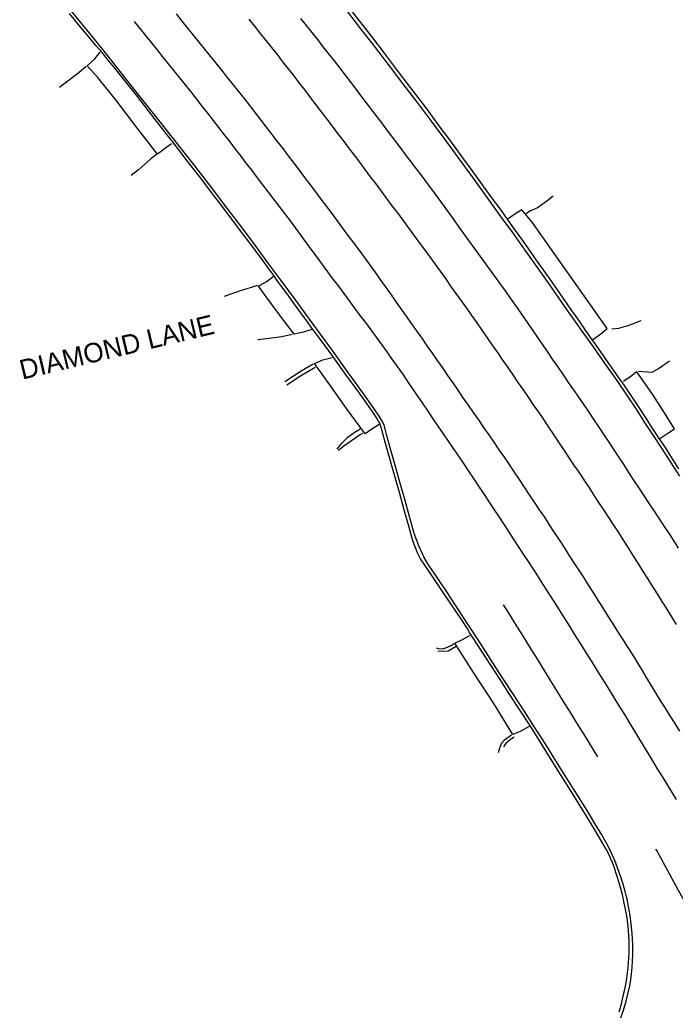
# Model space of a CAD drawing. Extents: x 1970211 to 1973046, y 801032 to 804001.
# Drawn here: x 1972654.2 to 1972835.3, y 801305.3 to 801579.3 of the extents above; entities that cross this region are included whole.
import ezdxf

# ---------------------------------------------------------------- set-up
doc = ezdxf.new("R2010")
doc.units = 0
for name, color, linetype in [('RD_EX_Conc', 7, 'Continuous'), ('RD_EX_Road', 7, 'Continuous'), ('RD_EX_Road_Paint', 7, 'Continuous'), ('RD_TX_RoadID', 7, 'Continuous')]:
    doc.layers.add(name, color=color, linetype=linetype)

msp = doc.modelspace()

# ---------------------------------------------------------------- linework, layer by layer
at = {"layer": 'RD_EX_Conc'}
for points in [[(1972745.68, 801581.99), (1972748.76, 801578.08), (1972751.65, 801574.34), (1972754.91, 801570.07), (1972759.07, 801564.57), (1972763.27, 801559.01), (1972766.66, 801554.53), (1972769.79, 801550.36), (1972773.24, 801545.72), (1972776.6, 801541.15), (1972779.45, 801537.2), (1972782.04, 801533.6), (1972784.61, 801530.07), (1972786.94, 801526.88), (1972788.82, 801524.26), (1972790.66, 801521.68), (1972792.86, 801518.58), (1972795.24, 801515.23), (1972797.6, 801511.88), (1972800.21, 801508.15), (1972803.36, 801503.66), (1972806.41, 801499.28), (1972808.77, 801495.9), (1972810.5, 801493.4), (1972811.7, 801491.67), (1972812.91, 801489.93), (1972814.66, 801487.43), (1972816.51, 801484.8), (1972817.98, 801482.67), (1972819.12, 801481.04), (1972819.96, 801479.91), (1972821.05, 801478.4), (1972822.93, 801475.62), (1972825.14, 801472.28), (1972827.22, 801469.1), (1972828.92, 801466.46), (1972830.02, 801464.76), (1972830.84, 801463.49), (1972831.75, 801462.13), (1972832.71, 801460.67), (1972833.7, 801459.13), (1972834.85, 801457.33), (1972836.29, 801455.1)], [(1972819.87, 801304.88), (1972820.39, 801306.73), (1972820.99, 801309.16), (1972821.51, 801311.47), (1972821.81, 801312.96), (1972822, 801314.16), (1972822.2, 801315.62), (1972822.37, 801317.13), (1972822.48, 801318.47), (1972822.56, 801319.8), (1972822.62, 801321.25), (1972822.64, 801322.81), (1972822.61, 801324.43), (1972822.55, 801325.96), (1972822.48, 801327.26), (1972822.35, 801328.58), (1972822.16, 801330.17), (1972821.9, 801331.9), (1972821.56, 801333.67), (1972821.19, 801335.37), (1972820.83, 801336.9), (1972820.5, 801338.22), (1972820.23, 801339.28), (1972819.86, 801340.57), (1972819.25, 801342.54), (1972818.57, 801344.6), (1972817.99, 801346.14), (1972817.46, 801347.35), (1972816.96, 801348.44), (1972816.22, 801349.87), (1972815, 801352.07), (1972813.15, 801355.21), (1972810.57, 801359.45), (1972807.41, 801364.52), (1972803.86, 801370.2), (1972800.43, 801375.68), (1972797.65, 801380.16), (1972795.14, 801384.16), (1972792.54, 801388.19), (1972789.86, 801392.3), (1972787.14, 801396.53), (1972784.4, 801400.8), (1972781.67, 801405), (1972779.59, 801408.18), (1972778.81, 801409.35), (1972778.54, 801409.77), (1972777.99, 801410.7), (1972776.06, 801413.69), (1972771.62, 801420.28), (1972767.13, 801426.96), (1972765, 801430.22), (1972764.14, 801431.82), (1972763.44, 801433.51), (1972762.87, 801435.2), (1972762.38, 801436.79), (1972761.71, 801439.2), (1972760.56, 801443.36), (1972759.13, 801448.52), (1972757.59, 801453.94), (1972756.2, 801458.82), (1972755.2, 801462.41), (1972754.5, 801464.89), (1972754.05, 801466.47), (1972753.77, 801467.38), (1972753.59, 801467.87), (1972753.38, 801468.28), (1972753, 801468.91), (1972752.03, 801470.34), (1972750.08, 801473.14), (1972747.34, 801477.01), (1972743.98, 801481.66), (1972740.63, 801486.29), (1972737.88, 801490.07), (1972735.89, 801492.8), (1972734.77, 801494.29), (1972733.72, 801495.71), (1972731.9, 801498.21), (1972729.84, 801501.04), (1972728.09, 801503.44), (1972726.65, 801505.4), (1972725.54, 801506.93), (1972724.76, 801508), (1972724.34, 801508.61), (1972723.97, 801509.16), (1972723.35, 801510.07), (1972721.97, 801511.96), (1972719.34, 801515.48), (1972716.13, 801519.75), (1972713.02, 801523.88), (1972710.03, 801527.83), (1972707.19, 801531.55), (1972704.21, 801535.45), (1972700.77, 801539.95), (1972697.92, 801543.66), (1972696.69, 801545.23), (1972695.64, 801546.56), (1972693.27, 801549.6), (1972690.06, 801553.75), (1972686.44, 801558.4), (1972683.04, 801562.72), (1972680.52, 801565.88), (1972678.68, 801568.14), (1972677.35, 801569.76), (1972676.48, 801570.8), (1972676, 801571.35), (1972675.27, 801572.19), (1972673.65, 801574.12), (1972671.19, 801577.08), (1972667.96, 801581)], [(1972696.13, 801545.02), (1972694.22, 801543.56), (1972692.31, 801542.12), (1972686.22, 801550), (1972681.01, 801556.76), (1972675.83, 801563.34), (1972672.82, 801566.6), (1972675, 801568.46), (1972676.43, 801570.33)], [(1972812.6, 801490.89), (1972814.78, 801492.4), (1972816.54, 801493.94), (1972811.93, 801500.41), (1972804.84, 801510.49), (1972795.85, 801523.29), (1972793, 801526.7), (1972791.03, 801525.49), (1972789.17, 801524.21)], [(1972734.94, 801493.66), (1972732.6, 801492.87), (1972730.03, 801492.33), (1972724.89, 801499.16), (1972720.22, 801505.57), (1972722.62, 801506.95), (1972724.27, 801508.25)], [(1972753.51, 801467.3), (1972751.49, 801466.04), (1972749.63, 801464.73), (1972744.53, 801471.76), (1972739.92, 801478.33), (1972735.69, 801484.23), (1972737.92, 801485.21), (1972740.54, 801485.88)], [(1972735.28, 801484.03), (1972732, 801482.05), (1972727.48, 801479.16)], [(1972831.12, 801463.48), (1972833.3, 801464.92), (1972835.16, 801466.1), (1972831.7, 801471.61), (1972828.85, 801476.03), (1972824.72, 801481.91), (1972822.79, 801480.44), (1972821.04, 801479.25)], [(1972748.9, 801464.88), (1972748.31, 801464.46), (1972743.78, 801461.39), (1972742.29, 801460.12)], [(1972794.94, 801383.77), (1972792.65, 801382.55), (1972790.44, 801381.62), (1972785.19, 801390.17), (1972779.64, 801398.71), (1972774.43, 801406.83), (1972776.37, 801407.75), (1972778.59, 801408.98)], [(1972769.28, 801405.52), (1972769.93, 801405.35), (1972771.07, 801405.29), (1972771.96, 801405.56), (1972773.44, 801406.22), (1972774.23, 801406.79)], [(1972790.8, 801380.8), (1972789.83, 801380.16), (1972789.12, 801379.56), (1972788.41, 801378.99), (1972787.92, 801378.17)]]:
    msp.add_lwpolyline(points, dxfattribs=at)
at = {"layer": 'RD_EX_Road'}
for points in [[(1972820.26, 801302.91), (1972821.06, 801305.35), (1972821.8, 801307.85), (1972822.37, 801310.09), (1972822.77, 801312.01), (1972823.06, 801313.77), (1972823.27, 801315.42), (1972823.43, 801317.14), (1972823.56, 801318.94), (1972823.64, 801320.55), (1972823.67, 801321.98), (1972823.65, 801323.43), (1972823.58, 801324.95), (1972823.47, 801326.58), (1972823.31, 801328.29), (1972823.11, 801329.93), (1972822.88, 801331.47), (1972822.63, 801332.97), (1972822.37, 801334.42), (1972822.12, 801335.64), (1972821.87, 801336.71), (1972821.48, 801338.19), (1972820.94, 801340.15), (1972820.25, 801342.35), (1972819.44, 801344.7), (1972818.66, 801346.76), (1972817.86, 801348.59), (1972816.68, 801350.91), (1972815.07, 801353.8), (1972813.17, 801357), (1972810.98, 801360.53), (1972808.33, 801364.76), (1972805.3, 801369.62), (1972802.36, 801374.32), (1972799.55, 801378.79), (1972796.63, 801383.38), (1972793.59, 801388.09), (1972790.66, 801392.61), (1972787.83, 801396.98), (1972784.75, 801401.72), (1972781.4, 801406.91), (1972777.89, 801412.34), (1972774.46, 801417.64), (1972772.43, 801420.75), (1972771.76, 801421.75), (1972770.87, 801423.07), (1972769.57, 801424.99), (1972768.32, 801426.79), (1972767.17, 801428.49), (1972765.89, 801430.77), (1972764.46, 801433.76), (1972763.12, 801437.48), (1972761.91, 801441.85), (1972760.69, 801446.29), (1972759.44, 801450.78), (1972758.05, 801455.75), (1972756.61, 801460.9), (1972755.76, 801463.96), (1972755.51, 801464.9), (1972755.32, 801465.66), (1972755.09, 801466.55), (1972754.79, 801467.4), (1972754.36, 801468.27), (1972753.5, 801469.64), (1972752.15, 801471.64), (1972750.17, 801474.46), (1972747.61, 801478.06), (1972744.72, 801482.08), (1972741.56, 801486.48), (1972738.08, 801491.29), (1972734.3, 801496.48), (1972730.41, 801501.79), (1972726.47, 801507.13), (1972722.6, 801512.38), (1972718.79, 801517.56), (1972714.81, 801522.86), (1972710.65, 801528.34), (1972706.34, 801533.96), (1972701.91, 801539.7), (1972697.43, 801545.44), (1972692.99, 801551.09), (1972688.98, 801556.18), (1972685.41, 801560.7), (1972682, 801565.01), (1972678.62, 801569.25), (1972674.84, 801573.94), (1972670.64, 801579.09), (1972666.32, 801584.32)], [(1972836.62, 801453.04), (1972834.12, 801456.92), (1972831.63, 801460.77), (1972829.12, 801464.61), (1972826.79, 801468.18), (1972824.6, 801471.55), (1972822.12, 801475.31), (1972819.28, 801479.53), (1972816.12, 801484.06), (1972812.72, 801488.79), (1972809.46, 801493.4), (1972806.36, 801497.83), (1972803.3, 801502.21), (1972800.24, 801506.58), (1972797.11, 801511.02), (1972793.9, 801515.55), (1972790.61, 801520.15), (1972787.19, 801524.87), (1972783.47, 801530.01), (1972779.47, 801535.56), (1972775.45, 801541.13), (1972771.46, 801546.59), (1972767.7, 801551.66), (1972764.13, 801556.37), (1972760.38, 801561.31), (1972756.43, 801566.51), (1972752.48, 801571.64), (1972748.5, 801576.78), (1972743.91, 801582.67)], [(1972672.54, 801566.36), (1972670.52, 801564.65), (1972666.79, 801561.73), (1972665.2, 801560.58)], [(1972692.03, 801542), (1972690.31, 801540.71), (1972687.02, 801537.83), (1972685.02, 801536.18)], [(1972801.65, 801530.48), (1972799.86, 801529.13), (1972797.28, 801527.29), (1972795.21, 801526.32), (1972794.14, 801525.65)], [(1972720, 801505.79), (1972715.14, 801504.29), (1972710.69, 801502.77)], [(1972817.87, 801493.76), (1972819.76, 801494.02), (1972822.33, 801494.72), (1972825.96, 801496.07)], [(1972729.52, 801492.25), (1972726.59, 801491.61), (1972722.4, 801491.04), (1972719.89, 801490.75)], [(1972728.01, 801478.33), (1972731.8, 801480.83), (1972735.89, 801483.17)], [(1972833.8, 801484.83), (1972831.02, 801482.91), (1972828.88, 801481.72), (1972825.2, 801482.01)], [(1972748.32, 801466.08), (1972746.37, 801464.82), (1972744.64, 801463.52), (1972742.82, 801461.83), (1972741.84, 801460.5)], [(1972774.77, 801405.88), (1972772.56, 801404.68), (1972771.26, 801404.52), (1972769.7, 801404.66)], [(1972786.53, 801376.63), (1972786.86, 801377.91), (1972787.45, 801379.25), (1972788.18, 801380.08), (1972790.13, 801381.46)]]:
    msp.add_lwpolyline(points, dxfattribs=at)
at = {"layer": 'RD_EX_Road_Paint'}
for points in [[(1972685.85, 801578.85), (1972687.41, 801576.9), (1972688.97, 801574.95), (1972690.53, 801572.99), (1972692.09, 801571.04), (1972693.65, 801569.09), (1972695.21, 801567.13), (1972696.77, 801565.18), (1972698.33, 801563.23), (1972699.89, 801561.27), (1972701.45, 801559.32), (1972703.01, 801557.37), (1972704.57, 801555.41), (1972706.1, 801553.44), (1972707.63, 801551.46), (1972709.17, 801549.49), (1972710.7, 801547.51), (1972712.22, 801545.53), (1972713.74, 801543.54), (1972715.26, 801541.56), (1972716.78, 801539.57), (1972718.3, 801537.59), (1972719.81, 801535.6), (1972721.33, 801533.62), (1972722.85, 801531.63), (1972724.37, 801529.65), (1972725.89, 801527.66), (1972727.41, 801525.68), (1972728.9, 801523.67), (1972730.38, 801521.65), (1972731.86, 801519.64), (1972733.33, 801517.62), (1972734.81, 801515.6), (1972736.3, 801513.6), (1972737.79, 801511.59), (1972739.28, 801509.58), (1972740.77, 801507.57), (1972742.26, 801505.57), (1972743.75, 801503.56), (1972745.24, 801501.55), (1972746.73, 801499.54), (1972748.22, 801497.53), (1972749.71, 801495.53), (1972751.2, 801493.52), (1972752.68, 801491.51), (1972754.14, 801489.48), (1972755.61, 801487.45), (1972757.07, 801485.43), (1972758.53, 801483.4), (1972759.94, 801481.34), (1972761.35, 801479.27), (1972762.76, 801477.2), (1972764.16, 801475.14), (1972765.57, 801473.07), (1972766.98, 801471), (1972768.38, 801468.94), (1972769.79, 801466.87), (1972771.2, 801464.8), (1972772.6, 801462.74), (1972774.01, 801460.67), (1972775.42, 801458.6), (1972776.82, 801456.53), (1972778.22, 801454.46), (1972779.62, 801452.39), (1972781.02, 801450.32), (1972782.4, 801448.24), (1972783.77, 801446.14), (1972785.13, 801444.05), (1972786.5, 801441.96), (1972787.87, 801439.86), (1972789.23, 801437.77), (1972790.6, 801435.68), (1972791.97, 801433.58), (1972793.33, 801431.49), (1972794.7, 801429.4), (1972796.07, 801427.3), (1972797.43, 801425.21), (1972798.78, 801423.11), (1972800.13, 801421), (1972801.47, 801418.89), (1972802.81, 801416.78), (1972804.15, 801414.67), (1972805.47, 801412.55), (1972806.79, 801410.42), (1972808.11, 801408.3), (1972809.43, 801406.18), (1972810.76, 801404.06), (1972812.08, 801401.94), (1972813.4, 801399.81), (1972814.72, 801397.69), (1972816.04, 801395.57), (1972817.36, 801393.45), (1972818.68, 801391.32), (1972819.99, 801389.19), (1972821.3, 801387.07), (1972822.61, 801384.94), (1972823.92, 801382.81), (1972825.22, 801380.67), (1972826.52, 801378.53), (1972827.81, 801376.4), (1972829.11, 801374.26), (1972830.4, 801372.12), (1972831.7, 801369.98), (1972832.99, 801367.84), (1972834.29, 801365.7), (1972835.58, 801363.56)], [(1972836.61, 801382.49), (1972835.29, 801384.61), (1972833.96, 801386.73), (1972832.64, 801388.85), (1972831.32, 801390.97), (1972830.03, 801393.11), (1972828.73, 801395.25), (1972827.43, 801397.38), (1972826.13, 801399.52), (1972824.83, 801401.65), (1972823.51, 801403.78), (1972822.18, 801405.89), (1972820.84, 801408), (1972819.5, 801410.11), (1972818.16, 801412.23), (1972816.83, 801414.34), (1972815.49, 801416.45), (1972814.15, 801418.56), (1972812.81, 801420.67), (1972811.48, 801422.79), (1972810.14, 801424.9), (1972808.79, 801427), (1972807.43, 801429.1), (1972806.07, 801431.2), (1972804.72, 801433.3), (1972803.36, 801435.4), (1972802, 801437.5), (1972800.64, 801439.6), (1972799.27, 801441.69), (1972797.88, 801443.76), (1972796.49, 801445.84), (1972795.1, 801447.92), (1972793.71, 801450), (1972792.32, 801452.08), (1972790.94, 801454.16), (1972789.55, 801456.24), (1972788.16, 801458.31), (1972786.74, 801460.37), (1972785.31, 801462.43), (1972783.89, 801464.48), (1972782.47, 801466.54), (1972781.05, 801468.59), (1972779.63, 801470.65), (1972778.2, 801472.71), (1972776.78, 801474.76), (1972775.36, 801476.82), (1972773.94, 801478.87), (1972772.51, 801480.93), (1972771.09, 801482.98), (1972769.66, 801485.04), (1972768.23, 801487.09), (1972766.8, 801489.14), (1972765.37, 801491.19), (1972763.94, 801493.24), (1972762.51, 801495.29), (1972761.07, 801497.33), (1972759.62, 801499.37), (1972758.18, 801501.41), (1972756.73, 801503.45), (1972755.28, 801505.49), (1972753.84, 801507.53), (1972752.39, 801509.56), (1972750.94, 801511.6), (1972749.46, 801513.61), (1972747.97, 801515.62), (1972746.49, 801517.63), (1972745, 801519.64), (1972743.51, 801521.65), (1972742.03, 801523.66), (1972740.54, 801525.67), (1972739.04, 801527.67), (1972737.54, 801529.67), (1972736.03, 801531.67), (1972734.53, 801533.67), (1972733.03, 801535.66), (1972731.52, 801537.66), (1972730.02, 801539.66), (1972728.52, 801541.66), (1972727.01, 801543.65), (1972725.48, 801545.62), (1972723.95, 801547.6), (1972722.42, 801549.58), (1972720.89, 801551.56), (1972719.36, 801553.54), (1972717.84, 801555.52), (1972716.31, 801557.49), (1972714.77, 801559.47), (1972713.21, 801561.42), (1972711.64, 801563.37), (1972710.08, 801565.32), (1972708.52, 801567.27), (1972706.95, 801569.22), (1972705.39, 801571.17), (1972703.83, 801573.12), (1972702.26, 801575.07), (1972700.69, 801577.01), (1972699.11, 801578.95), (1972697.54, 801580.9)], [(1972835.74, 801412.05), (1972834.42, 801414.17), (1972833.1, 801416.29), (1972831.76, 801418.41), (1972830.43, 801420.52), (1972829.09, 801422.64), (1972827.76, 801424.75), (1972826.42, 801426.86), (1972825.09, 801428.98), (1972823.75, 801431.09), (1972822.42, 801433.2), (1972821.09, 801435.32), (1972819.73, 801437.42), (1972818.36, 801439.51), (1972817, 801441.6), (1972815.63, 801443.7), (1972814.26, 801445.79), (1972812.89, 801447.88), (1972811.53, 801449.97), (1972810.14, 801452.06), (1972808.76, 801454.14), (1972807.37, 801456.22), (1972805.99, 801458.3), (1972804.6, 801460.38), (1972803.22, 801462.46), (1972801.83, 801464.55), (1972800.44, 801466.62), (1972799.03, 801468.68), (1972797.61, 801470.75), (1972796.2, 801472.81), (1972794.79, 801474.87), (1972793.38, 801476.94), (1972791.97, 801479), (1972790.56, 801481.06), (1972789.14, 801483.12), (1972787.72, 801485.18), (1972786.29, 801487.23), (1972784.87, 801489.29), (1972783.45, 801491.34), (1972782.03, 801493.4), (1972780.61, 801495.46), (1972779.18, 801497.51), (1972777.75, 801499.56), (1972776.29, 801501.59), (1972774.83, 801503.62), (1972773.37, 801505.65), (1972771.92, 801507.68), (1972770.46, 801509.71), (1972769, 801511.74), (1972767.54, 801513.77), (1972766.08, 801515.8), (1972764.59, 801517.81), (1972763.11, 801519.82), (1972761.62, 801521.83), (1972760.13, 801523.84), (1972758.65, 801525.85), (1972757.16, 801527.86), (1972755.68, 801529.87), (1972754.19, 801531.88), (1972752.69, 801533.88), (1972751.18, 801535.88), (1972749.68, 801537.87), (1972748.17, 801539.87), (1972746.67, 801541.87), (1972745.16, 801543.86), (1972743.66, 801545.86), (1972742.15, 801547.85), (1972740.65, 801549.85), (1972739.13, 801551.83), (1972737.61, 801553.82), (1972736.09, 801555.81), (1972734.57, 801557.79), (1972733.05, 801559.78), (1972731.54, 801561.76), (1972730.02, 801563.75), (1972728.5, 801565.73), (1972726.95, 801567.7), (1972725.4, 801569.66), (1972723.85, 801571.62), (1972722.3, 801573.58), (1972720.75, 801575.54), (1972719.2, 801577.5), (1972717.65, 801579.47)], [(1972836.26, 801433.14), (1972834.92, 801435.25), (1972833.55, 801437.34), (1972832.18, 801439.42), (1972830.81, 801441.51), (1972829.43, 801443.6), (1972828.06, 801445.69), (1972826.69, 801447.78), (1972825.31, 801449.87), (1972823.94, 801451.96), (1972822.57, 801454.05), (1972821.2, 801456.14), (1972819.82, 801458.23), (1972818.45, 801460.32), (1972817.08, 801462.41), (1972815.7, 801464.5), (1972814.33, 801466.58), (1972812.96, 801468.67), (1972811.55, 801470.74), (1972810.14, 801472.8), (1972808.73, 801474.86), (1972807.31, 801476.93), (1972805.9, 801478.99), (1972804.49, 801481.05), (1972803.07, 801483.11), (1972801.66, 801485.18), (1972800.25, 801487.24), (1972798.84, 801489.3), (1972797.42, 801491.36), (1972796.01, 801493.43), (1972794.6, 801495.49), (1972793.18, 801497.55), (1972791.77, 801499.61), (1972790.33, 801501.66), (1972788.87, 801503.68), (1972787.4, 801505.71), (1972785.94, 801507.73), (1972784.47, 801509.76), (1972783.01, 801511.79), (1972781.54, 801513.81), (1972780.08, 801515.84), (1972778.61, 801517.86), (1972777.15, 801519.89), (1972775.68, 801521.91), (1972774.22, 801523.94), (1972772.75, 801525.97), (1972771.29, 801527.99), (1972769.82, 801530.02), (1972768.36, 801532.04), (1972766.87, 801534.05), (1972765.37, 801536.05), (1972763.86, 801538.04), (1972762.35, 801540.04), (1972760.84, 801542.03), (1972759.34, 801544.02), (1972757.83, 801546.02), (1972756.32, 801548.01), (1972754.81, 801550.01), (1972753.31, 801552), (1972751.8, 801554), (1972750.29, 801555.99), (1972748.78, 801557.98), (1972747.28, 801559.98), (1972745.77, 801561.97), (1972744.26, 801563.97), (1972742.74, 801565.95), (1972741.19, 801567.91), (1972739.64, 801569.87), (1972738.09, 801571.83), (1972736.54, 801573.8), (1972734.99, 801575.76), (1972733.44, 801577.72), (1972731.89, 801579.68)], [(1972814, 801375.41), (1972812.68, 801377.53), (1972811.37, 801379.66), (1972810.05, 801381.78), (1972808.73, 801383.91), (1972807.41, 801386.03), (1972806.1, 801388.16), (1972804.78, 801390.28), (1972803.46, 801392.41), (1972802.15, 801394.53), (1972800.83, 801396.66), (1972799.51, 801398.78), (1972798.19, 801400.91), (1972796.88, 801403.03), (1972795.56, 801405.15), (1972794.24, 801407.28), (1972792.92, 801409.4), (1972791.61, 801411.53), (1972790.29, 801413.65), (1972788.97, 801415.78), (1972787.93, 801417.46)], [(1972857.77, 801301.84), (1972856.5, 801303.99), (1972855.22, 801306.14), (1972853.95, 801308.29), (1972852.67, 801310.44), (1972851.39, 801312.59), (1972850.12, 801314.74), (1972848.84, 801316.89), (1972847.56, 801319.04), (1972846.29, 801321.19), (1972845.01, 801323.34), (1972843.73, 801325.49), (1972842.46, 801327.64), (1972841.18, 801329.79), (1972839.91, 801331.94), (1972838.63, 801334.09), (1972837.42, 801336.27), (1972836.22, 801338.47), (1972835.03, 801340.66), (1972833.83, 801342.86), (1972832.64, 801345.06), (1972831.44, 801347.25), (1972830.25, 801349.45), (1972830, 801349.9)]]:
    msp.add_lwpolyline(points, dxfattribs=at)

# ---------------------------------------------------------------- texts
at = {"layer": 'RD_TX_RoadID'}
msp.add_text('DIAMOND LANE', height=5.4, rotation=13.4572, dxfattribs=at).set_placement((1972654.91, 801479.74))

doc.saveas('drawing.dxf')
